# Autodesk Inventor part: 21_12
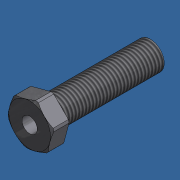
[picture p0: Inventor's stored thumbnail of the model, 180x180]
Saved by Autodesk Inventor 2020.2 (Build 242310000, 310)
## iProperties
Part Number: 21_12
Material: Generic
Document SubType Name: Modeling
Designer: amoles
Appearance: Default
Author: amoles
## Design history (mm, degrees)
feature "Base1"
thread "Thread1" dims "d0" = 74.2, "d1" = 0
body "Solid1"
